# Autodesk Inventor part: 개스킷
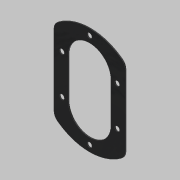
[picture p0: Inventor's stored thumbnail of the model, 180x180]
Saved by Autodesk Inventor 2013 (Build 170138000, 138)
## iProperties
Created: 2019-03
Part Number: 개스킷
Material: 고무
Document SubType Name: Modeling
Designer: mduedu
Density: 1 g/cm^3
Author: mduedu
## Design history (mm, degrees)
sketch "스케치1"
  geometry: L1 (-44.721, -40)-(44.721, -40); L2 (44.721, 40)-(-44.721, 40); A1 r 60 centre (0, 0) between (44.721, -40) and (44.721, 40); A2 r 60 centre (0, 0) between (-44.721, 40) and (-44.721, -40); 5 further points
  constraints: 6 point on circle, 4 end point, 2 centre point, 2 coincident, 2 horizontal alignment, 2 midpoint, 2 vertical alignment, 1 horizontal, 1 parallel
  dimensions: "d0" = 60 radius of A1; "d2" = 80 distance between parallel lines of L2 L1
extrude "돌출1" new body sketch "스케치1" distance "d3" = 1; taper "d4" = 0 deg
fillet "모깎기1" dims "d5" = 10
sketch "스케치2" dims "d6" = 48
  geometry: L1 (-24, -22)-(24, -22); L2 (24, -22)-(24, 22); L3 (24, 22)-(-24, 22); L4 (-24, 22)-(-24, -22); L5 (-24, -22)-(24, 22); L6 (24, -22)-(-24, 22); 3 further points
  constraints: 12 end point, 4 midpoint, 2 horizontal alignment, 2 parallel, 1 horizontal, 1 perpendicular, 4 other
  dimensions: "d8" = 22 distance from line of L3 point (0, 0)
extrude "돌출2" cut sketch "스케치2" stored distance "d9" = 1; taper "d10" = 0 deg
sketch "스케치3" dims "d0" = 60, "d2" = 80
  geometry: L1 (31, -22)-(31, 22); L2 (-31, 22)-(-31, -22); L3 (-31, -22)-(31, 22); L4 (31, -22)-(-31, 22); A1 r 31 centre (0, 22) between (31, 22) and (-31, 22); A2 r 31 centre (0, -22) between (-31, -22) and (31, -22); 8 further points
  constraints: 8 end point, 6 point on circle, 4 coincident, 4 midpoint, 3 tangent, 2 centre point, 2 vertical alignment, 1 parallel
  dimensions: "d11" = 31 radius of A1; "d13" = 44 distance of A2.centre A1.centre
hole "구멍1" sketch "스케치3" at (-31, 22), (-31, -22), (31, -22), (31, 22), (0, -53), (0, 53) diameter "d14" = 5.5; stored, may be unused: countersink angle "d18" = 90 deg, drill point angle "d20" = 118 deg; dims "d15" = 6, "d16" = 4, "d17" = 2, "d19" = 8
node "솔리드1"
